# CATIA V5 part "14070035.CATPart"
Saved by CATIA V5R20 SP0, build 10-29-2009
Part number: 14070035
Definition: NONE
Nomenclature: 14070035
Source: Unknown
Description: 14070035
Bounding box of the stored display mesh (mm): x -17.5 to 70, y -49 to 39.1, z -39.1 to 39.1
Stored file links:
  C:\Users\Utente\Desktop\IO LAVORO\3D X SITO CF\X SITO\PLASTICA\RF2\14070035.CATPart
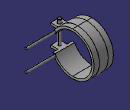
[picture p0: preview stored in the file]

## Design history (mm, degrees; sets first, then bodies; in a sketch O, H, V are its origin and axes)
Body1 "14070035" (main body)
  Solid1: solid without history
